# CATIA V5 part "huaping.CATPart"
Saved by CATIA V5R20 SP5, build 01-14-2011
Part number: 花瓶
Material "Bordeaux Red": density 7860 kg/m3, Young's modulus 2e+11 Pa, Poisson ratio 0.266
Material "Bordeaux Red": density 7860 kg/m3, Young's modulus 2e+11 Pa, Poisson ratio 0.266
Material "Bordeaux Red": density 7860 kg/m3, Young's modulus 2e+11 Pa, Poisson ratio 0.266
Bounding box of the stored display mesh (mm): x -40 to 40, y -40 to 45.921, z -0.446 to 139.494
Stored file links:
  E:\180212220\huaping.CATPart
  C:\Program Files\Dassault Systemes\B20\intel_a\startup\materials\Catalog.CATMaterial
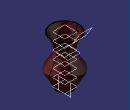
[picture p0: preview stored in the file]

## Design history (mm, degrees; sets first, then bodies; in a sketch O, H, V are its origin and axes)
Set1, material "Bordeaux Red"
  Plane1: type Offset, RefPlane xy-plane, Offset 20
  Plane2: type Offset, RefPlane Plane1, Offset 20
  Plane3: type Offset, RefPlane Plane2, Offset 20
  Plane4: type Offset, RefPlane Plane3, Offset 20
  Plane5: type Offset, RefPlane Plane4, Offset 20
  Plane6: type Offset, RefPlane Plane5, Offset 20
  Sketch1 on Plane2, origin (0, 0, 40), H (1, 0, 0), V (0, 1, 0)
    circle A1 centre (0, 0) radius 40
    radius A1 = 40
  Sketch2 on xy-plane, origin (0, 0, 0), H (1, 0, 0), V (0, 1, 0)
    circle A1 centre (0, 0) radius 20
    radius A1 = 20
  Sketch3 on Plane1, origin (0, 0, 20), H (1, 0, 0), V (0, 1, 0)
    circle A1 centre (0, 0) radius 30
    radius A1 = 30
  Sketch4 on Plane3, origin (0, 0, 60), H (1, 0, 0), V (0, 1, 0)
    circle A1 centre (0, 0) radius 30
    point P1 (30, 0)
    distance P1 V = 30
    radius A1 = 30
    coincidence: A1 P1
  Sketch5 on Plane4, origin (0, 0, 80), H (1, 0, 0), V (0, 1, 0)
    circle A1 centre (0, 0) radius 20
    radius A1 = 20
  Sketch6 on Plane5, origin (0, 0, 100), H (1, 0, 0), V (0, 1, 0)
    circle A1 centre (0, 0) radius 25
    radius A1 = 25
  Sketch7 on Plane6, origin (0, 0, 120), H (1, 0, 0), V (0, 1, 0)
    circle A1 centre (0, 0) radius 35
    radius A1 = 35
Body1 (main body), material "Bordeaux Red"
  Loft1: solid, Sections (Sketch2; Sketch3; Sketch1; Sketch4; Sketch5; Sketch6; Sketch7)
  Shell1: ExtOffset 0, Face face of Loft1, IntOffset 1
  Sketch8 on yz-plane, origin (0, 0, 0), H (0, 1, 0), V (0, 0, 1)
    spline S1 through (0, 0) (9.2169, 27.8774) (10.5995, 97.4849) (40.5555, 137.9169) (45.3945, 135.6197)
    point P1 (0, 0)
    coincidence: P1 O
  Plane7: type Normal, Curve Sketch8
  Plane8: type Normal, Curve Sketch8, RefPoint vertex of Sketch8
  Sketch9 on yz-plane, origin (0, 0, 0), H (0, 1, 0), V (0, 0, 1)
    spline S1 through (0, 40.1874) (34.2885, 40.1874)
    spline S2 through (34.2885, 40.1874) (28.6154, 21.0445) (18.3601, 0)
    line L1 (18.3601, 0) -> (0, 0)
    point P1 (18.3601, 0)
    axis line L2 (0, 1.0315) -> (0, 120.2394)
    point P2 (0, 1.0315)
    point P4 (0, 40.1874)
    point P5 (34.2885, 40.1874)
    point P6 (34.2885, 40.1874)
    point P7 (18.3601, 0)
    coincidence: P4 V, P5 P6, P7 H, P7 P1, P2 V
    horizontal: L1 H
    vertical: L2 V
  Shaft1: profile Sketch9, axis Sketch9.L2, angle 360
  Sketch10 on Plane8, origin (0, -28.9381, 18.3413), H (1, 0, 0), V (0, 0.5353, 0.8446)
    circle A1 centre (0, 138.835) radius 1
    point P1 (0, 138.835)
    radius A1 = 1
    coincidence: P1 V
  Rib1: profile Sketch10, centre curve Sketch8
